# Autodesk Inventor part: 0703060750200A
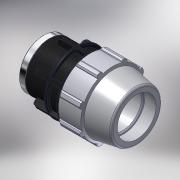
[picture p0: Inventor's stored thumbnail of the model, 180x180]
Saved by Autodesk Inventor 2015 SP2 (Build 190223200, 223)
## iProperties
Created: 2017-02
Part Number: 0703060750200A
Material: PVC-Piping
Description: PLASSON FEMALE ADAPTOR 75-2"
Document SubType Name: Modeling
Designer: KIM
Mass: 92.6774 g
Surface Area: 199.44 cm^2
Volume: 66.1981 cm^3
Density: 1.4 g/cm^3
Appearance: PTFE
Author: KIM
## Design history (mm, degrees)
derived "87030.ipt"
feature "Solid1::87030.ipt"
tag "TaggingFeature1"
body "Solid1"
other parameters: "d2" = 75, "d4" = 25, "d5" = 43.75, "d7" = 132, "d9" = 25, "d11" = 5, "d12" = 105.6, "d13" = 120 deg, "d14" = 97.5, "d15" = 10 deg, "d16" = 118.8, "d18" = 3.75, "d19" = 35 deg, "d20" = 17.5 deg, "d21" = 122.76, "d23" = 0, "d25" = 360 deg, "d27" = 2.64, "d34" = 6.6, "d35" = 52.5, "d36" = 0, "d42" = 43.75, "d43" = 3.96, "d46" = 2.25, "d49" = 132, "d51" = 175, "d53" = 1.5, "d55" = 360 deg, "d62" = 48.75, "d63" = 56.656, "d64" = 58.33333, "d65" = 6.6, "d69" = 95.04, "d70" = 3.3, "d71" = 12.6, "d72" = 0.5, "d73" = 1, "d_" = 75, "E_" = 132, "H_" = 175, "l_" = 132, "Rp_Rc_" = 56.656
